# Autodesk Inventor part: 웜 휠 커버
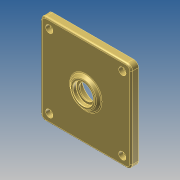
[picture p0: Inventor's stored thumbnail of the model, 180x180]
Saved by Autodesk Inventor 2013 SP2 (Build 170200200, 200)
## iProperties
Created: 2025-06
Part Number: 웜 휠 커버
Material: Generic
Document SubType Name: Modeling
Designer: i
Density: 1 g/cm^3
Author: i
변환 표준: STEP AP214IS
전처리기: Build: 200, Release: 2013 SP2 Update 6 - Date: Thu 07/17/2014
전송 단위: 밀리미터
불확실성: 0.01
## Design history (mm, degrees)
node "웜 휠 커버1"
node "솔리드1"
node "기준1"
